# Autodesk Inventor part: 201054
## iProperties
Created: 2007-10
Part Number: 201054
Document SubType Name: Modeling
Designer: TH
Density: 7.85 g/cm^3
Mass: 44.1035 g
Surface Area: 50.9461 cm^2
Volume: 5.61828 cm^3
Material: Steel
Description: CORNER BRACKET
Component Category: Lower Component
Author: TH
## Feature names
1. Extrusion1
2. Fillet1
3. Shell1
4. Extrusion2
5. Extrusion3
6. Fillet2
7. Hole1
8. Hole2
